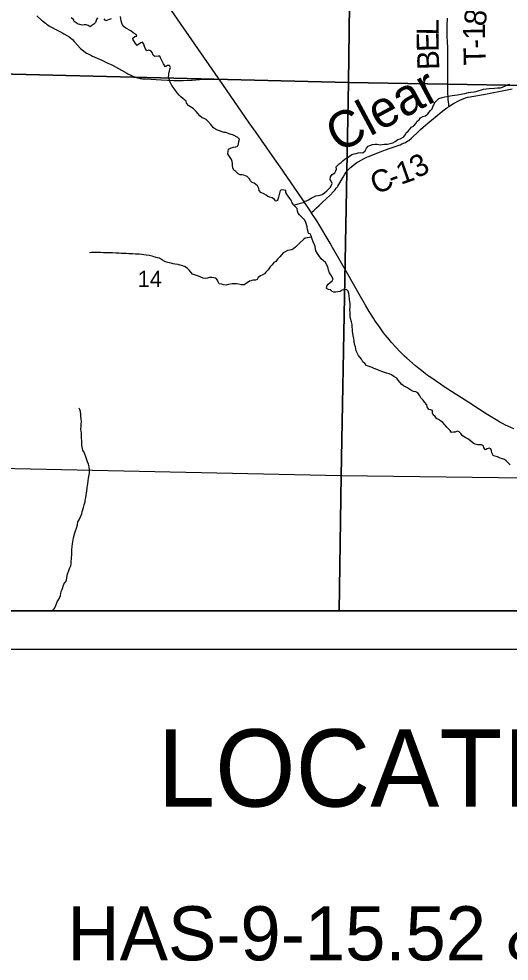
# Model space of a CAD drawing. Extents: x 0 to 34, y 0 to 22.
# Drawn here: x 12.568 to 13.836, y 12.694 to 15.132 of the extents above; entities that cross this region are included whole.
import ezdxf

# ---------------------------------------------------------------- set-up
doc = ezdxf.new("R2010")
doc.units = 0
for name, color, linetype in [('GM_X_Corporation', 7, 'Continuous'), ('GM_X_County_Road', 7, 'Continuous'), ('GM_X_County_Road_Text', 7, 'Continuous'), ('GM_X_Minor_River', 7, 'Continuous'), ('GM_X_Minor_River_Text', 7, 'Continuous'), ('GM_X_Section_Text', 7, 'Continuous'), ('GM_X_State_Route', 7, 'Continuous'), ('GM_X_Township_Road', 7, 'Continuous'), ('GM_X_Township_Road_Text', 7, 'Continuous'), ('SH_Data', 7, 'Continuous'), ('SH_Text', 7, 'Continuous')]:
    doc.layers.add(name, color=color, linetype=linetype)

msp = doc.modelspace()

# ---------------------------------------------------------------- linework, layer by layer
at = {"layer": 'GM_X_Corporation'}
for points in [[(12.4291, 16.0062), (13.4336, 15.974), (13.4208, 14.9679), (12.4126, 14.9928)], [(13.4336, 15.974), (14.4583, 15.9623), (14.443, 14.9501), (13.4208, 14.9679)], [(12.4126, 14.9928), (13.4208, 14.9679), (13.4018, 13.9496), (12.3963, 13.9711)], [(13.4208, 14.9679), (14.443, 14.9501), (14.4181, 13.9369), (13.4018, 13.9496)], [(12.3898, 13.6), (13.3964, 13.6), (13.4018, 13.9496), (12.3963, 13.9711)], [(13.3964, 13.6), (14.411, 13.6), (14.4181, 13.9369), (13.4018, 13.9496)]]:
    msp.add_lwpolyline(points, close=True, dxfattribs=at)
msp.add_lwpolyline([(10.9052, 15.3502), (10.897, 14.5214), (10.8818, 13.7678), (10.8788, 13.6), (16.4214, 13.6), (16.4212, 13.6609), (16.4339, 14.3806), (16.438, 14.5908), (16.4419, 14.8642), (16.4498, 15.4626)], dxfattribs=at)
at = {"layer": 'GM_X_County_Road'}
for points in [[(12.6147, 15.1398), (12.6266, 15.129), (12.6292, 15.1267), (12.6371, 15.1207), (12.6397, 15.1187), (12.6462, 15.1145), (12.6493, 15.1128), (12.6672, 15.1031), (12.6794, 15.0967), (12.6848, 15.0937), (12.694, 15.0882), (12.6971, 15.0861), (12.7035, 15.0811), (12.7059, 15.0792), (12.7116, 15.0736), (12.7131, 15.0719), (12.7267, 15.0566), (12.7279, 15.0555), (12.7351, 15.0492), (12.7366, 15.0482), (12.7434, 15.0436), (12.746, 15.0421), (12.7542, 15.0378), (12.7586, 15.0356), (12.7827, 15.0249), (12.7985, 15.0178), (12.8066, 15.0138), (12.8118, 15.0112), (12.8473, 14.9914), (12.8502, 14.9899), (12.8591, 14.9857), (12.8645, 14.9832), (12.8679, 14.9819), (12.8722, 14.9805), (12.8758, 14.9795), (12.8785, 14.9787), (12.882, 14.978), (12.8853, 14.9776), (12.8875, 14.9773), (12.8942, 14.9767), (12.8975, 14.9766), (12.9362, 14.9744), (12.9687, 14.9725), (12.9725, 14.9724), (12.993, 14.9725), (13.014, 14.9735), (13.016, 14.9736), (13.0447, 14.9757), (13.0487, 14.9758), (13.0842, 14.9762), (13.0862, 14.9763)], [(13.3242, 14.6313), (13.3254, 14.6322), (13.3316, 14.6374), (13.3381, 14.6431), (13.3445, 14.649), (13.3535, 14.6578), (13.3719, 14.6755), (13.3823, 14.6859), (13.385, 14.689), (13.3889, 14.6938), (13.3917, 14.6978), (13.3929, 14.6995), (13.4064, 14.7224), (13.41, 14.7285), (13.4129, 14.7328), (13.4154, 14.7362), (13.419, 14.7407), (13.4227, 14.7446), (13.426, 14.7478), (13.429, 14.7504), (13.4351, 14.7553), (13.4422, 14.7604), (13.4456, 14.7626), (13.4533, 14.7669), (13.4591, 14.77), (13.4676, 14.774), (13.4725, 14.7761), (13.4923, 14.7839), (13.5025, 14.7877), (13.5258, 14.7963), (13.5539, 14.8066), (13.5587, 14.8084), (13.5652, 14.8112), (13.5677, 14.8125), (13.574, 14.8163), (13.5763, 14.8178), (13.5833, 14.8235), (13.585, 14.825), (13.6009, 14.8401), (13.6067, 14.8456), (13.6201, 14.8576), (13.625, 14.8617), (13.6603, 14.8906), (13.6676, 14.8964), (13.6746, 14.9016), (13.6805, 14.9057), (13.6815, 14.9064), (13.6875, 14.9102), (13.6923, 14.913), (13.7053, 14.9201), (13.7097, 14.9222), (13.7173, 14.9254), (13.7227, 14.9275), (13.7287, 14.9294), (13.7303, 14.9298), (13.7786, 14.938), (13.7867, 14.9395), (13.8138, 14.9451), (13.8435, 14.9513)]]:
    msp.add_lwpolyline(points, dxfattribs=at)
at = {"layer": 'GM_X_Minor_River'}
for points in [[(12.7718, 15.1348), (12.7692, 15.1302), (12.7662, 15.123), (12.7624, 15.1184), (12.7571, 15.1146), (12.7525, 15.1116), (12.7476, 15.1154), (12.7419, 15.1165), (12.7373, 15.1169), (12.732, 15.1161), (12.7263, 15.1172), (12.7214, 15.1184), (12.7164, 15.1222), (12.7111, 15.1256), (12.7092, 15.1301), (12.7035, 15.1347)], [(12.8068, 15.1322), (12.8018, 15.1307), (12.7973, 15.1291), (12.7927, 15.1272), (12.7889, 15.1325)], [(12.9668, 14.9551), (12.9637, 14.9596), (12.961, 14.9653), (12.9584, 14.9699), (12.9568, 14.9763), (12.9549, 14.9816), (12.9557, 14.9862), (12.9564, 14.9915), (12.9579, 14.9965), (12.9586, 15.0022), (12.9602, 15.0067), (12.9579, 15.0113), (12.9529, 15.0117), (12.9472, 15.0082), (12.9419, 15.0162), (12.9346, 15.031), (12.9327, 15.0355), (12.9282, 15.0355), (12.9198, 15.0344), (12.9153, 15.0382), (12.9126, 15.045), (12.9091, 15.0496), (12.9042, 15.0515), (12.8989, 15.0495), (12.8951, 15.056), (12.8932, 15.0609), (12.8912, 15.0666), (12.8878, 15.0716), (12.8833, 15.0704), (12.8787, 15.0666), (12.8738, 15.0632), (12.87, 15.0685), (12.8669, 15.073), (12.8635, 15.0776), (12.8631, 15.0822), (12.868, 15.0867), (12.8733, 15.0871), (12.8718, 15.0917), (12.8642, 15.0958), (12.8577, 15.1011), (12.8452, 15.108), (12.8406, 15.1117), (12.8364, 15.1163), (12.8341, 15.1209), (12.833, 15.1273), (12.8318, 15.1319), (12.8307, 15.1383)], [(13.3347, 14.5427), (13.3324, 14.5476), (13.329, 14.5548), (13.3267, 14.5624), (13.3236, 14.5708), (13.3217, 14.5757), (13.3172, 14.5768), (13.316, 14.5814), (13.3149, 14.5871), (13.3133, 14.5939), (13.3122, 14.6), (13.3103, 14.6053), (13.3076, 14.6114), (13.303, 14.616), (13.2984, 14.6209), (13.2935, 14.6247), (13.2908, 14.6296), (13.2885, 14.6349), (13.2874, 14.6418), (13.2828, 14.6463), (13.2786, 14.6513), (13.2748, 14.6562), (13.2721, 14.6626), (13.2687, 14.6676), (13.2645, 14.6733), (13.2607, 14.6786), (13.2588, 14.6831), (13.2588, 14.6877), (13.2538, 14.6885), (13.2481, 14.69), (13.2436, 14.6881), (13.2417, 14.6812), (13.2394, 14.6709), (13.2372, 14.6618), (13.2326, 14.6603), (13.2292, 14.6648), (13.2228, 14.6694), (13.2171, 14.6705), (13.2121, 14.6724), (13.2075, 14.6758), (13.2015, 14.6792), (13.1939, 14.6826), (13.1897, 14.6883), (13.1885, 14.6929), (13.1855, 14.6997), (13.1763, 14.7073), (13.1718, 14.7088), (13.1672, 14.7134), (13.1634, 14.7195), (13.1588, 14.724), (13.1542, 14.7263), (13.1497, 14.7278), (13.1451, 14.7282), (13.1406, 14.7289), (13.1352, 14.7308), (13.1292, 14.7369), (13.1238, 14.7403), (13.1212, 14.7464), (13.1204, 14.7528), (13.1204, 14.7574), (13.12, 14.7627), (13.1177, 14.7684), (13.1142, 14.7737), (13.1112, 14.7783), (13.1089, 14.7828), (13.1093, 14.79), (13.11, 14.7946), (13.1172, 14.7988), (13.1233, 14.8003), (13.129, 14.8011), (13.1339, 14.8026), (13.1362, 14.8083), (13.1369, 14.8148), (13.1384, 14.8209), (13.1346, 14.8254), (13.1232, 14.8311), (13.1148, 14.8337), (13.1034, 14.8379), (13.0989, 14.8383), (13.0939, 14.8398), (13.0867, 14.8424), (13.0814, 14.8439), (13.0764, 14.8466), (13.0719, 14.8504), (13.0646, 14.8584), (13.057, 14.8675), (13.0524, 14.872), (13.0475, 14.8739), (13.0418, 14.8762), (13.0365, 14.8815), (13.0266, 14.8921), (13.0189, 14.9001), (13.0075, 14.9073), (13.0018, 14.9141), (13.0007, 14.9194), (12.9919, 14.9262), (12.9873, 14.9304), (12.9824, 14.935), (12.9786, 14.9403), (12.9736, 14.9471), (12.9668, 14.9551)], [(13.2793, 14.6505), (13.2964, 14.6551), (13.3029, 14.6574), (13.3074, 14.6604), (13.312, 14.6612), (13.3169, 14.6642), (13.3241, 14.6684), (13.3306, 14.6719), (13.3359, 14.6738), (13.3423, 14.6749), (13.3476, 14.6757), (13.3526, 14.678), (13.3583, 14.6822), (13.3647, 14.6868), (13.3692, 14.6913), (13.3742, 14.697), (13.3779, 14.7062), (13.376, 14.7119), (13.3733, 14.7168), (13.3737, 14.7233), (13.3786, 14.729), (13.3851, 14.7335), (13.3881, 14.7389), (13.3892, 14.7434), (13.3888, 14.7495), (13.396, 14.7567), (13.4013, 14.7609), (13.4062, 14.7644), (13.4115, 14.7701), (13.4168, 14.7724), (13.4229, 14.7765), (13.429, 14.7811), (13.435, 14.7827), (13.4404, 14.7838), (13.4453, 14.7853), (13.4517, 14.7861), (13.4574, 14.7857), (13.4639, 14.7907), (13.4669, 14.7972), (13.4711, 14.8029), (13.4756, 14.8048), (13.4828, 14.8074), (13.4893, 14.8078), (13.4942, 14.8078), (13.5026, 14.8063), (13.5075, 14.8067), (13.5124, 14.8075), (13.5215, 14.8083), (13.528, 14.8094), (13.5352, 14.8113), (13.5409, 14.8144), (13.5481, 14.8201), (13.5541, 14.822), (13.5636, 14.8273), (13.5678, 14.8327), (13.57, 14.8372), (13.5746, 14.8414), (13.5833, 14.8521), (13.589, 14.8555), (13.5947, 14.8616), (13.5981, 14.8673), (13.603, 14.8711), (13.6068, 14.8764), (13.6128, 14.8795), (13.62, 14.8814), (13.6253, 14.8867), (13.6321, 14.8947), (13.6367, 14.8993), (13.6386, 14.9042), (13.6416, 14.9122), (13.645, 14.9168), (13.6499, 14.9214), (13.6544, 14.9263), (13.6624, 14.929), (13.67, 14.9305), (13.6791, 14.9321), (13.6886, 14.9336), (13.6958, 14.9347), (13.7019, 14.9359), (13.7163, 14.9382), (13.7209, 14.9394), (13.7311, 14.9413), (13.7364, 14.9424), (13.7451, 14.9432), (13.7508, 14.9443), (13.758, 14.9466), (13.7641, 14.9489), (13.7694, 14.9501), (13.7763, 14.9509), (13.7846, 14.952), (13.7983, 14.9528), (13.8059, 14.9536), (13.8131, 14.954), (13.8191, 14.9555), (13.8263, 14.9589), (13.832, 14.9616), (13.8377, 14.9631)], [(13.3248, 14.5676), (13.3088, 14.5647), (13.3039, 14.5612), (13.2952, 14.5536), (13.2895, 14.5471), (13.2839, 14.541), (13.2793, 14.538), (13.2744, 14.5346), (13.2683, 14.5338), (13.2626, 14.533), (13.2569, 14.5292), (13.2516, 14.5269), (13.2478, 14.522), (13.2433, 14.5163), (13.2369, 14.5106), (13.2323, 14.5045), (13.2278, 14.5014), (13.2229, 14.4961), (13.2179, 14.4904), (13.213, 14.4831), (13.2066, 14.4771), (13.2032, 14.4725), (13.1975, 14.4691), (13.1926, 14.4671), (13.1873, 14.4626), (13.1842, 14.4576), (13.1797, 14.4561), (13.1736, 14.4557), (13.1649, 14.453), (13.1558, 14.4473), (13.1509, 14.4443), (13.1437, 14.4435), (13.1357, 14.4458), (13.1307, 14.4465), (13.1247, 14.4469), (13.1197, 14.4465), (13.1099, 14.4446), (13.1045, 14.443), (13.0977, 14.4442), (13.0932, 14.4453), (13.0859, 14.4464), (13.0833, 14.4517), (13.0817, 14.4563), (13.0772, 14.4612), (13.0673, 14.4631), (13.0612, 14.4627), (13.0563, 14.4616), (13.0513, 14.4601), (13.0445, 14.4616), (13.0384, 14.4638), (13.0327, 14.4661), (13.0168, 14.4714), (13.0141, 14.476), (13.0088, 14.482), (13.0042, 14.4866), (12.9985, 14.4908), (12.992, 14.4934), (12.9856, 14.4949), (12.9802, 14.4964), (12.9723, 14.4975), (12.9673, 14.4983), (12.9624, 14.4998), (12.9567, 14.5006), (12.9502, 14.5028), (12.9457, 14.504), (12.9396, 14.5074), (12.932, 14.5127), (12.9263, 14.5138), (12.9175, 14.5168), (12.913, 14.5183), (12.9054, 14.5199), (12.8978, 14.521), (12.8917, 14.5217), (12.8864, 14.5225), (12.8792, 14.5229), (12.8697, 14.5236), (12.8621, 14.524), (12.8572, 14.5243), (12.8526, 14.5243), (12.8458, 14.5247), (12.8382, 14.5247), (12.8329, 14.5251), (12.8264, 14.5258), (12.8188, 14.5262), (12.8105, 14.5269), (12.7983, 14.5269), (12.793, 14.5265), (12.7873, 14.5269), (12.7797, 14.5272), (12.7721, 14.5276), (12.7675, 14.528), (12.7562, 14.528), (12.7512, 14.5268)], [(13.7012, 14.0654), (13.6967, 14.0631), (13.6921, 14.0627), (13.6872, 14.062), (13.6834, 14.0673), (13.675, 14.0756), (13.6693, 14.0817), (13.6647, 14.0874), (13.6586, 14.092), (13.6529, 14.0954), (13.6484, 14.098), (13.6442, 14.103), (13.6396, 14.1075), (13.6377, 14.1121), (13.6377, 14.1189), (13.6327, 14.1208), (13.6278, 14.1212), (13.6236, 14.1284), (13.6228, 14.133), (13.6175, 14.1394), (13.6137, 14.1451), (13.6076, 14.1519), (13.6053, 14.1565), (13.5996, 14.1645), (13.5943, 14.1671), (13.5886, 14.1683), (13.5817, 14.1713), (13.5711, 14.1785), (13.5631, 14.1827), (13.5582, 14.1861), (13.5532, 14.1918), (13.5486, 14.1975), (13.5452, 14.2028), (13.5376, 14.207), (13.5315, 14.2107), (13.5254, 14.2134), (13.519, 14.2157), (13.514, 14.2172), (13.5083, 14.2191), (13.5023, 14.221), (13.4867, 14.2278), (13.4821, 14.2297), (13.4715, 14.2331), (13.4669, 14.235), (13.4631, 14.2403), (13.4578, 14.2445), (13.454, 14.2517), (13.4467, 14.2608), (13.4429, 14.2676), (13.4406, 14.2733), (13.4395, 14.2786), (13.4383, 14.2832), (13.4364, 14.2904), (13.4349, 14.298), (13.4345, 14.3052), (13.4329, 14.3128), (13.4318, 14.3189), (13.431, 14.3235), (13.4306, 14.3292), (13.4302, 14.3341), (13.4298, 14.341), (13.4279, 14.3478), (13.426, 14.3566), (13.4252, 14.3626), (13.4248, 14.3714), (13.424, 14.379), (13.4244, 14.387), (13.4244, 14.3953), (13.4236, 14.401), (13.4232, 14.4056), (13.4224, 14.4162), (13.4212, 14.4216), (13.4197, 14.4273), (13.4151, 14.4318), (13.4102, 14.431), (13.4041, 14.4299), (13.3988, 14.4268), (13.3928, 14.4261), (13.3878, 14.4249), (13.3829, 14.4253), (13.3783, 14.4264), (13.3738, 14.4306), (13.3688, 14.4317), (13.3639, 14.4344), (13.3642, 14.4405), (13.3676, 14.4454), (13.3779, 14.4542), (13.3805, 14.4591), (13.3786, 14.4637), (13.3748, 14.4701), (13.3717, 14.4754), (13.3691, 14.4823), (13.3679, 14.4868), (13.3649, 14.4956), (13.361, 14.5017), (13.3549, 14.5073), (13.3496, 14.5115), (13.3439, 14.5199), (13.3401, 14.5252), (13.3363, 14.5316), (13.3347, 14.5427)], [(12.7412, 13.8939), (12.7423, 13.9), (12.7427, 13.9049), (12.7449, 13.9182), (12.7457, 13.9243), (12.7468, 13.9289), (12.7475, 13.9369), (12.7483, 13.9433), (12.749, 13.9483), (12.7505, 13.957), (12.7509, 13.965), (12.7497, 13.9734), (12.7482, 13.9802), (12.7455, 13.9863), (12.7428, 13.9935), (12.7413, 13.9992), (12.7386, 14.0057), (12.7367, 14.011), (12.734, 14.0155), (12.7325, 14.0201), (12.7313, 14.0281), (12.7309, 14.0357), (12.7309, 14.0414), (12.7305, 14.0463), (12.7301, 14.0604), (12.7293, 14.0649), (12.7286, 14.0703), (12.7289, 14.0782), (12.7297, 14.0832), (12.73, 14.09), (12.7293, 14.0976), (12.7285, 14.1033), (12.7281, 14.1083), (12.7273, 14.1159), (12.7262, 14.1212), (12.7244, 14.1249)], [(13.8389, 13.9778), (13.8324, 13.9839), (13.8282, 13.9888), (13.8237, 13.9919), (13.8183, 13.9934), (13.8123, 13.9953), (13.8054, 13.9987), (13.799, 14.0002), (13.7944, 14.0024), (13.791, 14.0093), (13.7902, 14.0142), (13.7887, 14.0195), (13.7841, 14.0214), (13.7792, 14.0195), (13.7746, 14.0172), (13.7704, 14.0222), (13.7693, 14.0275), (13.7647, 14.0302), (13.759, 14.0298), (13.7545, 14.0298), (13.748, 14.0313), (13.7431, 14.0339), (13.7358, 14.04), (13.729, 14.0453), (13.724, 14.0483), (13.7149, 14.0536), (13.7107, 14.059), (13.7065, 14.0639), (13.7012, 14.0654)], [(12.6561, 13.6), (12.657, 13.6018), (12.6615, 13.6079), (12.6634, 13.614), (12.6672, 13.6239), (12.6732, 13.633), (12.6755, 13.6398), (12.6777, 13.6505), (12.68, 13.6554), (12.6849, 13.6695), (12.6894, 13.676), (12.6913, 13.6805), (12.692, 13.6851), (12.6935, 13.6927), (12.6988, 13.7102), (12.7022, 13.7167), (12.7033, 13.722), (12.7037, 13.7285), (12.7041, 13.7345), (12.7044, 13.7391), (12.7048, 13.7448), (12.7051, 13.7513), (12.7055, 13.7581), (12.7059, 13.7669), (12.7066, 13.7737), (12.7077, 13.779), (12.7092, 13.7889), (12.713, 13.8026), (12.7145, 13.8075), (12.7171, 13.8144), (12.7201, 13.8231), (12.7209, 13.8311), (12.7239, 13.8361), (12.7307, 13.8513), (12.7322, 13.8562), (12.7356, 13.868), (12.7367, 13.8749), (12.7393, 13.8821), (12.7401, 13.8867), (12.7412, 13.8939)]]:
    msp.add_lwpolyline(points, dxfattribs=at)
at = {"layer": 'GM_X_State_Route'}
for points in [[(13.1543, 14.8773), (13.0862, 14.9763), (13.0837, 14.9799), (13.0233, 15.0671), (12.9632, 15.1541)], [(13.8476, 14.0714), (13.8327, 14.0779), (13.8261, 14.081), (13.8185, 14.0849), (13.8118, 14.0886), (13.8063, 14.0919), (13.7898, 14.102), (13.7761, 14.1105), (13.7592, 14.1211), (13.7312, 14.1391), (13.6681, 14.1804), (13.6587, 14.1866), (13.6332, 14.2039), (13.625, 14.2097), (13.6185, 14.2145), (13.602, 14.2274), (13.5939, 14.234), (13.5858, 14.241), (13.5717, 14.2538), (13.5654, 14.2597), (13.5517, 14.2734), (13.5446, 14.2809), (13.5312, 14.2957), (13.5262, 14.3015), (13.5156, 14.3146), (13.5113, 14.3201), (13.5021, 14.3325), (13.4978, 14.3385), (13.489, 14.3515), (13.485, 14.3576), (13.4741, 14.3752), (13.4648, 14.391), (13.4513, 14.414), (13.4152, 14.4775), (13.3792, 14.5409), (13.3728, 14.5519), (13.3413, 14.6052), (13.3386, 14.6093), (13.3242, 14.6313), (13.322, 14.6345), (13.3024, 14.6636), (13.2703, 14.7105), (13.2437, 14.749), (13.2232, 14.7782), (13.1815, 14.8379), (13.1639, 14.8633), (13.1543, 14.8773)]]:
    msp.add_lwpolyline(points, dxfattribs=at)
at = {"layer": 'GM_X_Township_Road'}
msp.add_lwpolyline([(13.6805, 14.9057), (13.6802, 14.9079), (13.6798, 14.9114), (13.6785, 14.9232), (13.6782, 14.9268), (13.6775, 14.9422), (13.6774, 14.9496), (13.6777, 15.0329), (13.6772, 15.061), (13.6768, 15.0705), (13.6757, 15.0892), (13.6752, 15.1026), (13.6756, 15.1214), (13.6761, 15.1281), (13.6766, 15.134)], dxfattribs=at)
at = {"layer": 'SH_Data'}
for points in [[(10.5, 20.5), (17.5, 20.5), (17.5, 13.5), (10.5, 13.5)], [(10.6, 20.4), (17.4, 20.4), (17.4, 13.6), (10.6, 13.6)]]:
    msp.add_lwpolyline(points, close=True, dxfattribs=at)

# ---------------------------------------------------------------- texts
at = {"layer": 'GM_X_County_Road_Text'}
for s, rotation, p in [('3', 28.4975, (13.5977, 14.7181)), ('1', 19.1574, (13.5554, 14.7025)), ('C', 22.2725, (13.4911, 14.6771)), ('-', 20.1038, (13.5337, 14.6946))]:
    msp.add_text(s, height=0.0568, rotation=rotation, dxfattribs=at).set_placement(p)
at = {"layer": 'GM_X_Minor_River_Text'}
msp.add_text('Clear', height=0.09473, rotation=28.2048, dxfattribs=at).set_placement((13.3949, 14.784))
at = {"layer": 'GM_X_Section_Text'}
msp.add_text('14', height=0.04186, rotation=0, dxfattribs=at).set_placement((12.8756, 14.4383))
at = {"layer": 'GM_X_Township_Road_Text'}
for s, rotation, p in [('8', 80.0894, (13.7732, 15.1107)), ('L', 89.3314, (13.6533, 15.0894)), ('E', 91.2044, (13.6542, 15.0474)), ('1', 90.8483, (13.7739, 15.0785)), ('-', 91.335, (13.7744, 15.0553)), ('B', 91.292, (13.6553, 15.0007)), ('T', 91.4016, (13.7755, 15.0128))]:
    msp.add_text(s, height=0.0568, rotation=rotation, dxfattribs=at).set_placement(p)
at = {"layer": 'SH_Text'}
for s, height, p in [('LOCATION MAP', 0.2, (12.9269, 13.0938)), ('HAS-9-15.52 & HAS-9-17.04', 0.14, (12.6938, 12.6959))]:
    msp.add_text(s, height=height, dxfattribs=at).set_placement(p)

doc.saveas('drawing.dxf')
